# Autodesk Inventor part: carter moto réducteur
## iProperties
Created: 2002-06
Part Number: carter moto réducteur
Material: Par défaut
Document SubType Name: Modélisation
Designer: REVEST Pierre
Control State: 0
Master: False
Checked Out: False
Shininess: 20.0
Length Units: 11269
Angle Units: 11279
Time Units: 11290
Mass Units: 11283
Length Display Precision: 3
Angle Display Precision: 2
Density: 0.0
Volumn: 0.0
Area: 0.0
PropertySet Name: Model Information
Author: REVEST Pierre
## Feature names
1. Extrusion1
2. Extrusion2
3. Extrusion3
4. Extrusion4
5. Extrusion5
6. Extrusion6
7. Congé1 [Fillet]
8. Extrusion7
9. Extrusion8
10. Extrusion9
11. Congé2 [Fillet]
12. Extrusion10
13. Extrusion11
